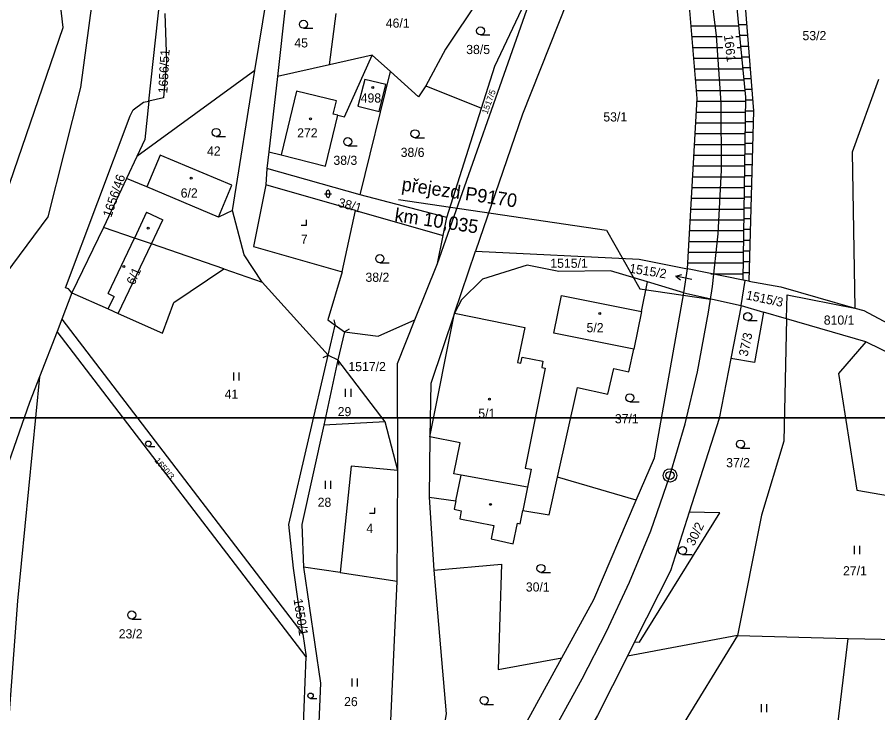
# Model space of a CAD drawing. Extents: x -553916 to -552953, y -1067470 to -1066637.
# Drawn here: x -553633.4 to -553473.7, y -1067154.7 to -1067025.6 of the extents above; entities that cross this region are included whole.
import ezdxf

# ---------------------------------------------------------------- set-up
doc = ezdxf.new("R2010")
doc.units = 0
for name, color, linetype in [('Hranice parcel', 7, 'Continuous'), ('Kolej', 7, 'Continuous'), ('Návěst místo trati', 7, 'Continuous'), ('Parcelní čísla', 7, 'Continuous'), ('Pop  PČ popisy', 7, 'Continuous'), ('Propustek', 7, 'Continuous'), ('Přejezd - štěrkové lože', 7, 'Continuous'), ('Vnitřní kresba', 7, 'Continuous'), ('Vrstva 1', 7, 'Continuous'), ('Značky budov', 7, 'Continuous'), ('Značky kultur', 7, 'Continuous')]:
    doc.layers.add(name, color=color, linetype=linetype)

msp = doc.modelspace()

# ---------------------------------------------------------------- linework, layer by layer
at = {"layer": 'Hranice parcel'}
for p, q in [((-553589.31, -1067035.5), (-553580.85, -1066983.77)), ((-553608.97, -1067041.18), (-553606.12, -1067014.56)), ((-553555.44, -1067071.33), (-553535.85, -1067015.85)), ((-553575.44, -1067034.44), (-553574.24, -1067024.96)), ((-553567.53, -1067032.65), (-553575.44, -1067034.44)), ((-553564.16, -1067035.68), (-553567.53, -1067032.65)), ((-553575.44, -1067034.44), (-553585.14, -1067036.63)), ((-553589.31, -1067035.5), (-553611.2, -1067051.45)), ((-553593.47, -1067061.49), (-553589.31, -1067035.5)), ((-553585.14, -1067036.63), (-553586.75, -1067050.6)), ((-553569.79, -1067058.6), (-553564.16, -1067035.68)), ((-553557.59, -1067038.38), (-553547.23, -1067042.51)), ((-553473.53, -1067037.17), (-553478.45, -1067050.68)), ((-553473.53, -1067037.17), (-553478.45, -1067050.68)), ((-553610, -1067041.4), (-553608.97, -1067041.18)), ((-553606.25, -1067040.6), (-553608.97, -1067041.18)), ((-553553.65, -1067062.79), (-553547.23, -1067042.51)), ((-553586.75, -1067050.6), (-553587.12, -1067053.68)), ((-553586.75, -1067050.6), (-553584.42, -1067051.17)), ((-553478.45, -1067050.68), (-553477.96, -1067079.63)), ((-553478.45, -1067050.68), (-553477.96, -1067079.63)), ((-553611.2, -1067051.45), (-553613.12, -1067055.53)), ((-553587.12, -1067053.68), (-553587.28, -1067056.75)), ((-553569.79, -1067058.6), (-553587.12, -1067053.68)), ((-553613.12, -1067055.53), (-553617.4, -1067064.65)), ((-553609.37, -1067057.11), (-553613.12, -1067055.53)), ((-553570.64, -1067061.48), (-553587.28, -1067056.75)), ((-553553.65, -1067062.79), (-553569.79, -1067058.6)), ((-553593.47, -1067061.49), (-553596.05, -1067062.7)), ((-553573.09, -1067072.86), (-553570.64, -1067061.48)), ((-553570.64, -1067061.48), (-553554.35, -1067066.11)), ((-553554.35, -1067066.11), (-553553.65, -1067062.79)), ((-553617.4, -1067064.65), (-553623.27, -1067076.77)), ((-553555.44, -1067071.33), (-553554.35, -1067066.11)), ((-553552.27, -1067080.57), (-553548.33, -1067069.03)), ((-553559.6, -1067081.76), (-553555.44, -1067071.33)), ((-553595.06, -1067072.35), (-553587.94, -1067074.8)), ((-553575.72, -1067088.37), (-553587.94, -1067074.8)), ((-553517.54, -1067080.21), (-553516.45, -1067074.75)), ((-553509.66, -1067076.78), (-553516.45, -1067074.75)), ((-553623.27, -1067076.77), (-553625.16, -1067081.69)), ((-553490.63, -1067081.59), (-553490.53, -1067077.13)), ((-553490.63, -1067081.59), (-553490.53, -1067077.13)), ((-553490.53, -1067077.13), (-553477.96, -1067079.63)), ((-553490.53, -1067077.13), (-553477.96, -1067079.63)), ((-553517.54, -1067080.21), (-553518.94, -1067087.24)), ((-553490.63, -1067081.59), (-553494.87, -1067080.36)), ((-553475.9, -1067085.87), (-553490.63, -1067081.59)), ((-553625.16, -1067081.69), (-553626.04, -1067083.95)), ((-553625.16, -1067081.69), (-553580.41, -1067140.15)), ((-553575.72, -1067088.37), (-553574.42, -1067082.75)), ((-553574.42, -1067082.75), (-553572.66, -1067084.02)), ((-553626.04, -1067083.95), (-553629.28, -1067092.37)), ((-553579.82, -1067144.32), (-553626.04, -1067083.95)), ((-553572.66, -1067084.02), (-553573.91, -1067089.23)), ((-553461.02, -1067093.19), (-553475.9, -1067085.87)), ((-553573.91, -1067089.23), (-553576.54, -1067101.32)), ((-553565.13, -1067100.69), (-553573.91, -1067089.23)), ((-553565.13, -1067100.69), (-553576.54, -1067101.32)), ((-553562.76, -1067109.76), (-553565.13, -1067100.69)), ((-553562.87, -1067130.27), (-553562.76, -1067109.76)), ((-553518.53, -1067115.26), (-553533.13, -1067110.99)), ((-553556.94, -1067114.69), (-553556.09, -1067128.27)), ((-553573.45, -1067128.7), (-553580.27, -1067127.69)), ((-553573.45, -1067128.7), (-553562.87, -1067130.27)), ((-553580.41, -1067140.15), (-553579.82, -1067144.32)), ((-553499.73, -1067140.34), (-553520.16, -1067144.23)), ((-553499.73, -1067140.34), (-553516.39, -1067167.53)), ((-553499.73, -1067140.34), (-553516.39, -1067167.53)), ((-553499.73, -1067140.34), (-553479.18, -1067140.92)), ((-553482.63, -1067169.28), (-553479.18, -1067140.92)), ((-553479.18, -1067140.92), (-553459.64, -1067141.29)), ((-553581.09, -1067176.52), (-553579.82, -1067144.32))]:
    msp.add_line(p, q, dxfattribs=at)
for points in [[(-553623.32, -1066984.67), (-553619.63, -1066996.83), (-553619.56, -1067023.02), (-553621.7, -1067038.64), (-553627.75, -1067062.69), (-553642.34, -1067082.27), (-553644.52, -1067088.87), (-553655.73, -1067178.24), (-553657.73, -1067185.13), (-553660.17, -1067189.87)], [(-553515.43, -1066991.08), (-553526.38, -1067010.19), (-553539.65, -1067043.59), (-553548.33, -1067069.03)], [(-553547.23, -1067042.51), (-553544.77, -1067034.69), (-553535.85, -1067015.85)], [(-553635.52, -1067058.6), (-553624.9, -1067027.54), (-553625.87, -1067018.94)], [(-553547.68, -1067022.12), (-553553.91, -1067031.58), (-553557.59, -1067038.38)], [(-553582.25, -1067023.44), (-553583.62, -1067023.18), (-553585.14, -1067036.63)], [(-553606.05, -1067024.93), (-553605.71, -1067033.75), (-553606.25, -1067040.6)], [(-553573.91, -1067043.82), (-553572.67, -1067044.12), (-553567.53, -1067032.65)], [(-553557.59, -1067038.38), (-553558.91, -1067040.42), (-553564.16, -1067035.68)], [(-553568.89, -1067037.19), (-553570.19, -1067042.13), (-553566.22, -1067043.1), (-553564.98, -1067038.12), (-553568.89, -1067037.19)], [(-553624.48, -1067075.84), (-553612.48, -1067043.92), (-553611.9, -1067042.79), (-553610, -1067041.4)], [(-553608.97, -1067041.18), (-553609.73, -1067048.33), (-553611.2, -1067051.45)], [(-553584.42, -1067051.17), (-553576.18, -1067053.25), (-553573.91, -1067043.82)], [(-553596.05, -1067062.7), (-553593.57, -1067056.8), (-553606.92, -1067051.2), (-553609.37, -1067057.11)], [(-553587.28, -1067056.75), (-553589.54, -1067068.19), (-553573.09, -1067072.86)], [(-553587.94, -1067074.8), (-553591.32, -1067069.72), (-553593.47, -1067061.49)], [(-553595.06, -1067072.35), (-553608.53, -1067067.7), (-553611.68, -1067066.62), (-553617.4, -1067064.65)], [(-553548.33, -1067069.03), (-553517.95, -1067070.55), (-553509.03, -1067072.35)], [(-553516.45, -1067074.75), (-553523.31, -1067072.7), (-553532.92, -1067072.84), (-553538.78, -1067071.62), (-553547.04, -1067074.23), (-553550.96, -1067078.08), (-553552.27, -1067080.57)], [(-553623.27, -1067076.77), (-553616.54, -1067079.76), (-553614.66, -1067080.6), (-553606.47, -1067084.24), (-553604.34, -1067078.59), (-553595.06, -1067072.35)], [(-553573.09, -1067072.86), (-553575.74, -1067081.8), (-553574.42, -1067082.75)], [(-553497.61, -1067074.62), (-553491.7, -1067075.64), (-553477.96, -1067079.63)], [(-553623.27, -1067076.77), (-553623.9, -1067076.05), (-553624.48, -1067075.84)], [(-553518.94, -1067087.24), (-553533.8, -1067084.25), (-553532.39, -1067077.24), (-553517.54, -1067080.21)], [(-553477.96, -1067079.63), (-553476.25, -1067080.06), (-553464.58, -1067086.32)], [(-553552.27, -1067080.57), (-553556.64, -1067093.58), (-553556.86, -1067103.5), (-553556.94, -1067114.69)], [(-553490.63, -1067081.59), (-553491.15, -1067104.31), (-553495.3, -1067118.01), (-553499.73, -1067140.34)], [(-553490.63, -1067081.59), (-553491.15, -1067104.31), (-553495.3, -1067118.01), (-553499.73, -1067140.34)], [(-553572.66, -1067084.02), (-553566.4, -1067084.81), (-553559.6, -1067081.76)], [(-553562.76, -1067109.76), (-553562.85, -1067089.89), (-553559.6, -1067081.76)], [(-553475.9, -1067085.87), (-553480.97, -1067091.73), (-553477.55, -1067113.39), (-553465.08, -1067115.55)], [(-553533.13, -1067110.99), (-553529.45, -1067094.35), (-553523.77, -1067095.61), (-553522.71, -1067090.83), (-553519.87, -1067091.46), (-553518.94, -1067087.24)], [(-553580.41, -1067140.15), (-553582.14, -1067127.86), (-553583, -1067119.78), (-553575.72, -1067088.37)], [(-553629.28, -1067092.37), (-553631.12, -1067097.14), (-553637.98, -1067116.48)], [(-553629.28, -1067092.37), (-553633.37, -1067133.92), (-553635.66, -1067164.7)], [(-553576.54, -1067101.32), (-553580.57, -1067119.79), (-553580.27, -1067127.69)], [(-553562.76, -1067109.76), (-553571.44, -1067108.95), (-553573.45, -1067128.7)], [(-553540.05, -1067119.63), (-553539.55, -1067117.17), (-553534.67, -1067117.97), (-553533.13, -1067110.99)], [(-553556.94, -1067114.69), (-553551.99, -1067115.38), (-553552.31, -1067116.95)], [(-553552.31, -1067116.95), (-553550.99, -1067117.22), (-553551.28, -1067118.69), (-553544.93, -1067119.96), (-553545.42, -1067122.41), (-553541.36, -1067123.37), (-553540.59, -1067119.53), (-553540.05, -1067119.63)], [(-553518.82, -1067141.56), (-553517.91, -1067141.59), (-553503, -1067117.58), (-553508.67, -1067117.46)], [(-553580.27, -1067127.69), (-553577.12, -1067149.23), (-553578.28, -1067177), (-553579.68, -1067182.05)], [(-553556.09, -1067128.27), (-553543.56, -1067127.12), (-553544.12, -1067146.66), (-553532.35, -1067144.53)], [(-553556.09, -1067128.27), (-553553.82, -1067154.93), (-553557.64, -1067176.88)], [(-553569.54, -1067184.03), (-553564.06, -1067156.23), (-553562.87, -1067130.27)]]:
    msp.add_lwpolyline(points, dxfattribs=at)
at = {"layer": 'Kolej'}
for points in [[(-553503.32, -1067065.81), (-553502.68, -1067054.03), (-553502.76, -1067041.5), (-553503.63, -1067029.06), (-553504.76, -1067019.97), (-553506.18, -1067011.39), (-553508.33, -1067001.39), (-553510.95, -1066991.62), (-553512.92, -1066985.29), (-553515.65, -1066977.35), (-553517.42, -1066972.53), (-553519.16, -1066967.95), (-553522.89, -1066958.38), (-553529.1, -1066942.55), (-553538.69, -1066918.11), (-553542.91, -1066907.33), (-553546.69, -1066897.68), (-553555.03, -1066876.44), (-553564.64, -1066851.89), (-553574.24, -1066827.43), (-553583.19, -1066804.62)], [(-553543.17, -1067173.82), (-553538.26, -1067165.53), (-553533.28, -1067156.93), (-553528.57, -1067148.43), (-553524.02, -1067139.63), (-553519.75, -1067130.49), (-553515.84, -1067120.93), (-553512.27, -1067110.73), (-553509.46, -1067101.06), (-553507.13, -1067091.41), (-553505.08, -1067080.38), (-553504.39, -1067075.58), (-553503.32, -1067065.81)]]:
    msp.add_lwpolyline(points, dxfattribs=at)
at = {"layer": 'Návěst místo trati'}
for radius in [1.25, 0.752]:
    msp.add_circle((-553512.25, -1067110.66), radius, dxfattribs=at)
at = {"layer": 'Pop  PČ popisy'}
for p, q in [((-553511.16, -1067073.68), (-553510.07, -1067073.4)), ((-553508.22, -1067074.31), (-553511.16, -1067073.68)), ((-553511.16, -1067073.68), (-553510.28, -1067074.38))]:
    msp.add_line(p, q, dxfattribs=at)
at = {"layer": 'Propustek'}
for p, q in [((-553499.28, -1067010.65), (-553496.78, -1067043.02)), ((-553508.33, -1067027.22), (-553499.45, -1067027.22)), ((-553499.48, -1067026.97), (-553498.02, -1067026.97)), ((-553508.16, -1067029.22), (-553502.6, -1067029.22)), ((-553500.05, -1067029.22), (-553499.26, -1067029.22)), ((-553499.28, -1067028.97), (-553497.87, -1067028.97)), ((-553508, -1067031.22), (-553502.47, -1067031.22)), ((-553499.81, -1067031.22), (-553499.06, -1067031.22)), ((-553499.09, -1067030.97), (-553497.71, -1067030.97)), ((-553507.83, -1067033.22), (-553498.87, -1067033.22)), ((-553498.89, -1067032.97), (-553497.56, -1067032.97)), ((-553507.67, -1067035.22), (-553498.67, -1067035.22)), ((-553498.7, -1067034.97), (-553497.4, -1067034.97)), ((-553507.51, -1067037.22), (-553498.48, -1067037.22)), ((-553498.51, -1067036.97), (-553497.25, -1067036.97)), ((-553507.34, -1067039.22), (-553498.29, -1067039.22)), ((-553498.31, -1067038.97), (-553497.09, -1067038.97)), ((-553507.25, -1067041.22), (-553498.18, -1067041.22)), ((-553498.18, -1067040.97), (-553496.94, -1067040.97)), ((-553507.37, -1067043.22), (-553498.21, -1067043.22)), ((-553498.21, -1067042.97), (-553496.78, -1067042.97)), ((-553496.78, -1067043.02), (-553497.61, -1067074.62)), ((-553507.48, -1067045.22), (-553498.24, -1067045.22)), ((-553498.24, -1067044.97), (-553496.83, -1067044.97)), ((-553507.59, -1067047.22), (-553498.27, -1067047.22)), ((-553498.27, -1067046.97), (-553496.88, -1067046.97)), ((-553507.71, -1067049.22), (-553498.3, -1067049.22)), ((-553498.3, -1067048.97), (-553496.94, -1067048.97)), ((-553507.82, -1067051.22), (-553498.33, -1067051.22)), ((-553498.33, -1067050.97), (-553496.99, -1067050.97)), ((-553507.94, -1067053.22), (-553498.36, -1067053.22)), ((-553498.36, -1067052.97), (-553497.04, -1067052.97)), ((-553508.05, -1067055.22), (-553498.39, -1067055.22)), ((-553498.39, -1067054.97), (-553497.09, -1067054.97)), ((-553508.17, -1067057.22), (-553498.42, -1067057.22)), ((-553498.42, -1067056.97), (-553497.15, -1067056.97)), ((-553508.28, -1067059.22), (-553498.45, -1067059.22)), ((-553498.45, -1067058.97), (-553497.2, -1067058.97)), ((-553508.39, -1067061.22), (-553498.48, -1067061.22)), ((-553498.48, -1067060.97), (-553497.25, -1067060.97)), ((-553508.51, -1067063.22), (-553498.51, -1067063.22)), ((-553498.51, -1067062.97), (-553497.3, -1067062.97)), ((-553508.62, -1067065.22), (-553498.54, -1067065.22)), ((-553498.54, -1067064.97), (-553497.36, -1067064.97)), ((-553508.74, -1067067.22), (-553498.57, -1067067.22)), ((-553498.57, -1067066.97), (-553497.41, -1067066.97)), ((-553508.85, -1067069.22), (-553498.6, -1067069.22)), ((-553498.6, -1067068.97), (-553497.46, -1067068.97)), ((-553508.97, -1067071.22), (-553498.63, -1067071.22)), ((-553498.63, -1067070.97), (-553497.51, -1067070.97)), ((-553498.68, -1067074.42), (-553509.03, -1067072.35)), ((-553504.67, -1067073.22), (-553498.66, -1067073.22)), ((-553498.66, -1067072.97), (-553497.57, -1067072.97)), ((-553498.28, -1067074.5), (-553498.68, -1067074.42)), ((-553497.61, -1067074.62), (-553498.28, -1067074.5))]:
    msp.add_line(p, q, dxfattribs=at)
for points in [[(-553498.68, -1067074.42), (-553498.17, -1067040.43), (-553500.08, -1067020.73), (-553503.77, -1067001.28), (-553507.63, -1066988.97), (-553505.83, -1066988.51)], [(-553509.03, -1067072.35), (-553507.22, -1067040.68), (-553509.18, -1067016.9), (-553515.22, -1066991.69), (-553515.43, -1066991.08)]]:
    msp.add_lwpolyline(points, dxfattribs=at)
at = {"layer": 'Přejezd - štěrkové lože'}
msp.add_lwpolyline([(-553562.67, -1067059.43), (-553524.03, -1067065.17), (-553517.87, -1067076.06), (-553504.74, -1067077.98)], dxfattribs=at)
at = {"layer": 'Vnitřní kresba'}
for p, q in [((-553581.57, -1067039.35), (-553584.42, -1067051.17)), ((-553574.19, -1067041.13), (-553581.57, -1067039.35)), ((-553574.78, -1067043.61), (-553574.19, -1067041.13)), ((-553573.91, -1067043.82), (-553574.78, -1067043.61)), ((-553596.05, -1067062.7), (-553609.37, -1067057.11)), ((-553609.4, -1067061.81), (-553611.68, -1067066.62)), ((-553609.4, -1067061.81), (-553606.41, -1067063.23)), ((-553608.53, -1067067.7), (-553606.41, -1067063.23)), ((-553616.56, -1067076.9), (-553611.68, -1067066.62)), ((-553614.66, -1067080.6), (-553608.53, -1067067.7)), ((-553616.56, -1067076.9), (-553615.43, -1067077.44)), ((-553616.54, -1067079.76), (-553615.43, -1067077.44)), ((-553556.86, -1067103.5), (-553552.27, -1067080.57)), ((-553552.27, -1067080.57), (-553539.23, -1067083.19)), ((-553574.63, -1067081.77), (-553574.42, -1067082.75)), ((-553539.23, -1067083.19), (-553540.54, -1067089.73)), ((-553571.8, -1067083.51), (-553572.66, -1067084.02)), ((-553576.63, -1067088.79), (-553575.72, -1067088.37)), ((-553575.72, -1067088.37), (-553573.91, -1067089.23)), ((-553573.64, -1067090.19), (-553573.91, -1067089.23)), ((-553539.93, -1067089.85), (-553539.7, -1067088.69)), ((-553539.7, -1067088.69), (-553535.83, -1067089.46)), ((-553535.83, -1067089.46), (-553536.06, -1067090.62)), ((-553540.54, -1067089.73), (-553539.93, -1067089.85)), ((-553535.4, -1067090.75), (-553539.11, -1067109.32)), ((-553536.06, -1067090.62), (-553535.4, -1067090.75)), ((-553551.22, -1067104.63), (-553556.86, -1067103.5)), ((-553552.37, -1067110.36), (-553551.22, -1067104.63)), ((-553551.04, -1067110.63), (-553552.37, -1067110.36)), ((-553539.11, -1067109.32), (-553538.03, -1067109.53)), ((-553538.03, -1067109.53), (-553538.68, -1067112.82)), ((-553551.99, -1067115.38), (-553551.04, -1067110.63)), ((-553538.68, -1067112.82), (-553551.04, -1067110.63)), ((-553538.68, -1067112.82), (-553539.55, -1067117.17))]:
    msp.add_line(p, q, dxfattribs=at)
at = {"layer": 'Vrstva 1'}
for p, q in [((-553509.66, -1067076.78), (-553509.03, -1067072.35)), ((-553499.07, -1067079.14), (-553498.28, -1067074.5)), ((-553509.66, -1067076.78), (-553499.07, -1067079.14)), ((-553499.07, -1067079.14), (-553500.97, -1067088.98)), ((-553499.07, -1067079.14), (-553494.87, -1067080.36)), ((-553518.82, -1067141.56), (-553520.16, -1067144.23))]:
    msp.add_line(p, q, dxfattribs=at)
for points in [[(-553300, -1066816.27), (-553300, -1067100), (-553800, -1067100), (-553800, -1066816.27)], [(-553518.53, -1067115.26), (-553515.16, -1067107.38), (-553509.66, -1067076.78)], [(-553494.87, -1067080.36), (-553496.55, -1067089.69), (-553500.97, -1067088.98)], [(-553500.97, -1067088.98), (-553503.12, -1067100.12), (-553508.67, -1067117.46)], [(-553800, -1067410.27), (-553800, -1067100), (-553300, -1067100), (-553300, -1067410.27)], [(-553532.35, -1067144.53), (-553526.4, -1067133.68), (-553518.53, -1067115.26)], [(-553508.67, -1067117.46), (-553512.16, -1067128.37), (-553518.82, -1067141.56)], [(-553551.38, -1067177.98), (-553539.14, -1067156.92), (-553532.35, -1067144.53)], [(-553520.16, -1067144.23), (-553525.7, -1067155.19), (-553540.6, -1067180.86)]]:
    msp.add_lwpolyline(points, dxfattribs=at)
at = {"layer": 'Značky budov'}
for centre in [(-553567.44, -1067038.66), (-553579, -1067044.5), (-553601.13, -1067055.48), (-553609.12, -1067064.77), (-553613.62, -1067071.87), (-553525.3, -1067080.61), (-553545.78, -1067096.51), (-553545.57, -1067116.03)]:
    msp.add_circle(centre, 0.175, dxfattribs=at)
at = {"layer": 'Značky kultur'}
for p, q in [((-553580.29, -1067027.68), (-553578.54, -1067027.68)), ((-553547.42, -1067028.91), (-553545.67, -1067028.91)), ((-553596.5, -1067047.76), (-553594.75, -1067047.76)), ((-553559.59, -1067048), (-553557.84, -1067048)), ((-553572.07, -1067049.47), (-553570.32, -1067049.47)), ((-553576.4, -1067058.4), (-553575.06, -1067058.4)), ((-553576.07, -1067058.06), (-553576.07, -1067058.74)), ((-553575.4, -1067058.74), (-553575.4, -1067058.06)), ((-553579.73, -1067064.23), (-553579.73, -1067063.23)), ((-553580.73, -1067064.23), (-553579.73, -1067064.23)), ((-553566.12, -1067071.18), (-553564.37, -1067071.18)), ((-553497.83, -1067081.93), (-553496.08, -1067081.93)), ((-553593.23, -1067093.03), (-553593.23, -1067091.53)), ((-553592.23, -1067093.03), (-553592.23, -1067091.53)), ((-553572.46, -1067096.09), (-553572.46, -1067094.59)), ((-553571.46, -1067096.09), (-553571.46, -1067094.59)), ((-553519.72, -1067097), (-553517.97, -1067097)), ((-553609.07, -1067105.28), (-553607.9, -1067105.28)), ((-553499.17, -1067105.6), (-553497.42, -1067105.6)), ((-553576.19, -1067113.16), (-553576.19, -1067111.66)), ((-553575.19, -1067113.16), (-553575.19, -1067111.66)), ((-553567.02, -1067117.68), (-553567.02, -1067116.68)), ((-553568.02, -1067117.68), (-553567.02, -1067117.68)), ((-553477.99, -1067125.26), (-553477.99, -1067123.76)), ((-553476.99, -1067125.26), (-553476.99, -1067123.76)), ((-553509.92, -1067125.35), (-553508.17, -1067125.35)), ((-553536.21, -1067128.68), (-553534.46, -1067128.68)), ((-553612.17, -1067137.31), (-553610.42, -1067137.31)), ((-553571.26, -1067149.83), (-553571.26, -1067148.33)), ((-553570.26, -1067149.83), (-553570.26, -1067148.33)), ((-553578.97, -1067152.05), (-553577.8, -1067152.05)), ((-553546.76, -1067153.17), (-553545.01, -1067153.17)), ((-553495.26, -1067154.62), (-553495.26, -1067153.12)), ((-553494.26, -1067154.62), (-553494.26, -1067153.12))]:
    msp.add_line(p, q, dxfattribs=at)
for centre, radius in [((-553580.29, -1067026.93), 0.75), ((-553547.42, -1067028.16), 0.75), ((-553596.5, -1067047.01), 0.75), ((-553572.07, -1067048.72), 0.75), ((-553559.59, -1067047.25), 0.75), ((-553566.12, -1067070.43), 0.75), ((-553497.83, -1067081.18), 0.75), ((-553519.72, -1067096.25), 0.75), ((-553609.08, -1067104.78), 0.502), ((-553499.17, -1067104.85), 0.75), ((-553509.92, -1067124.6), 0.75), ((-553536.21, -1067127.93), 0.75), ((-553612.17, -1067136.56), 0.75), ((-553578.98, -1067151.55), 0.502), ((-553546.76, -1067152.42), 0.75)]:
    msp.add_circle(centre, radius, dxfattribs=at)
for centre, start, end in [((-553575.73, -1067058.07), 0, 180), ((-553575.73, -1067058.74), 180, 359.9879)]:
    msp.add_arc(centre, 0.335, start, end, dxfattribs=at)

# ---------------------------------------------------------------- texts
at = {"layer": 'Parcelní čísla'}
for s, p in [('46/1', (-553565.01, -1067027.56)), ('53/2', (-553487.66, -1067029.88)), ('45', (-553581.98, -1067031.23)), ('38/5', (-553550.08, -1067032.46)), ('498', (-553569.67, -1067041.46)), ('53/1', (-553524.63, -1067044.97)), ('272', (-553581.46, -1067047.94)), ('42', (-553598.19, -1067051.31)), ('38/3', (-553574.73, -1067053.02)), ('38/6', (-553562.25, -1067051.55)), ('6/2', (-553603.08, -1067059.09)), ('7', (-553580.77, -1067067.65)), ('1515/1', (-553534.47, -1067072.13)), ('38/2', (-553568.78, -1067074.73)), ('810/1', (-553483.71, -1067082.68)), ('5/2', (-553527.74, -1067084.08)), ('1517/2', (-553571.95, -1067091.31)), ('41', (-553594.93, -1067096.42)), ('29', (-553573.94, -1067099.66)), ('5/1', (-553547.84, -1067100)), ('37/1', (-553522.49, -1067100.99)), ('37/2', (-553501.83, -1067109.15)), ('28', (-553577.66, -1067116.49)), ('4', (-553568.62, -1067121.33)), ('27/1', (-553480.14, -1067129.21)), ('30/1', (-553539.01, -1067132.21)), ('23/2', (-553614.58, -1067140.91)), ('26', (-553572.75, -1067153.48))]:
    msp.add_text(s, height=1.7, dxfattribs=at).set_placement(p)
for s, height, rotation, p in [('1656/51', 1.7, 87, (-553605.56, -1067039.79)), ('1517/5', 1.14, 70, (-553546.16, -1067043.69)), ('1656/46', 1.7, 71, (-553615.99, -1067062.91)), ('38/1', 1.7, 345, (-553574, -1067060.76)), ('6/1', 1.7, 66, (-553611.68, -1067075.45)), ('1515/3', 1.7, 348, (-553498.25, -1067077.96)), ('1650/3', 1.14, 310, (-553608.01, -1067107.95)), ('30/2', 1.7, 64, (-553507.8, -1067123.87)), ('1650/1', 1.7, 279, (-553582.15, -1067133.66))]:
    msp.add_text(s, height=height, rotation=rotation, dxfattribs=at).set_placement(p)
at = {"layer": 'Přejezd - štěrkové lože'}
for s, p in [('přejezd P9170', (-553562.17, -1067057.78)), ('km 10,035', (-553563.49, -1067063.48))]:
    msp.add_text(s, height=2.5, rotation=351.5622, dxfattribs=at).set_placement(p)
at = {"layer": 'Vrstva 1'}
for s, rotation, p in [('1661', 276.6165, (-553502.25, -1067028.98)), ('1515/2', 351, (-553519.91, -1067073.02)), ('37/3', 78, (-553497.86, -1067088.69))]:
    msp.add_text(s, height=1.7, rotation=rotation, dxfattribs=at).set_placement(p)

doc.saveas('drawing.dxf')
